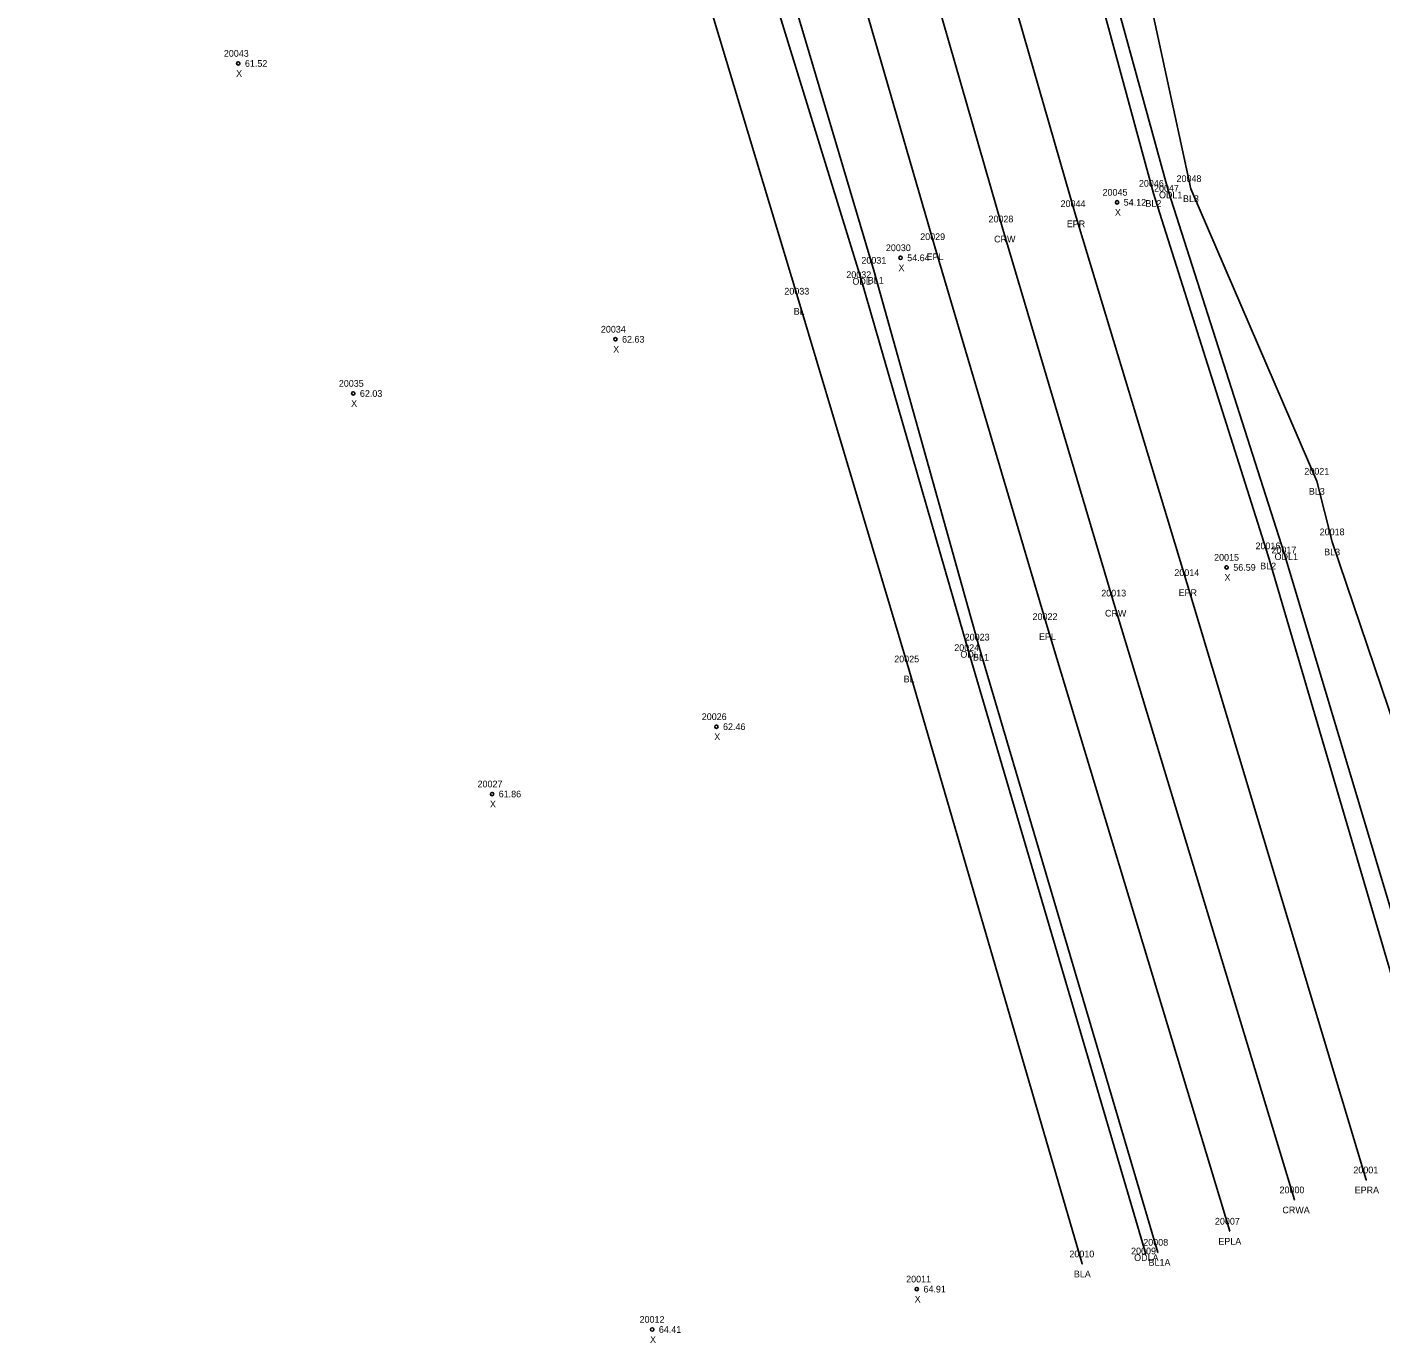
# Model space of a CAD drawing. Extents: x 2445178 to 2446260, y 791158 to 792318.
# Drawn here: x 2445670.7 to 2445873, y 791157.7 to 791354.3 of the extents above; entities that cross this region are included whole.
import ezdxf

# ---------------------------------------------------------------- set-up
doc = ezdxf.new("R2010")
doc.units = 0
for name, color, linetype in [('RD_DTM_BkLn1', 7, 'Continuous'), ('RD_EX_H2O', 7, 'Continuous'), ('RD_EX_H2O_txCode', 7, 'Continuous'), ('RD_EX_Road', 7, 'Continuous'), ('RD_EX_Road_txCode', 7, 'Continuous'), ('RD_Sketch8', 7, 'Continuous'), ('RD_SMD_Locator', 7, 'Continuous'), ('RD_SMD_Misc', 7, 'Continuous')]:
    doc.layers.add(name, color=color, linetype=linetype)

msp = doc.modelspace()

# ---------------------------------------------------------------- linework, layer by layer
at = {"layer": 'RD_DTM_BkLn1'}
for points in [[(2445860.1, 791179.04), (2445833.11, 791268.21), (2445816.53, 791324.11), (2445799.46, 791383.44), (2445783.89, 791440.59), (2445769.57, 791497.35), (2445755.95, 791556.11), (2445741.36, 791625.36), (2445732.84, 791671.31), (2445721.28, 791739.8), (2445717.39, 791765.43)], [(2445882.78, 791184.78), (2445856.18, 791275.27), (2445839.04, 791329.43), (2445822.96, 791388.68), (2445805.7, 791444.65), (2445792.52, 791499.62), (2445777.56, 791559.78), (2445760.75, 791635.11), (2445757, 791668.89), (2445761.65, 791682.26), (2445806.3, 791698.85), (2445844.78, 791714.67)], [(2445896.2, 791187.37), (2445865.75, 791277.36), (2445863.45, 791286.42), (2445844.64, 791330.14), (2445831.75, 791389.47), (2445816.24, 791445.72), (2445804.21, 791499.93), (2445790.09, 791561.7), (2445779.57, 791613.54), (2445773.51, 791630.61), (2445764.7, 791668.39), (2445768.27, 791675.25), (2445808.12, 791695.24), (2445844.78, 791714.67)], [(2445839.71, 791171.21), (2445812.99, 791261.63), (2445797.26, 791317.94), (2445780.39, 791374.8), (2445762.73, 791434.98), (2445748.42, 791490.93), (2445737.04, 791541.96), (2445736.07, 791553.56), (2445730.12, 791555.63), (2445697.6, 791546.96), (2445670.73, 791536.08)], [(2445828.38, 791169.47), (2445802.46, 791258.37), (2445786.04, 791313.32), (2445768.83, 791370.56), (2445749.12, 791431.66), (2445737.78, 791488.28), (2445729.51, 791541.48), (2445729.31, 791548.76), (2445698.8, 791542.8), (2445670.73, 791536.08)]]:
    msp.add_lwpolyline(points, dxfattribs=at)
at = {"layer": 'RD_EX_H2O'}
for points in [[(2445885.63, 791185.34), (2445858.54, 791275.66), (2445841.27, 791329.71), (2445824.98, 791389.05), (2445808.2, 791445.07), (2445795.15, 791500.08), (2445780.4, 791559.92), (2445764.43, 791632.51), (2445759.72, 791668.56), (2445764.88, 791679.11), (2445806.8, 791696.09), (2445844.78, 791714.67)], [(2445837.89, 791170.92), (2445811.42, 791261.06), (2445795.3, 791316.79), (2445777.82, 791373.49), (2445760.55, 791434.46), (2445746.47, 791490.55), (2445734.66, 791541.55), (2445732.29, 791551.98), (2445698.31, 791545.12), (2445670.73, 791536.08)]]:
    msp.add_lwpolyline(points, dxfattribs=at)
at = {"layer": 'RD_EX_Road'}
for points in [[(2445850.42, 791174.36), (2445823.13, 791264.7), (2445806.34, 791321.46), (2445789.41, 791379.89), (2445773.46, 791437.57), (2445759.36, 791494.22), (2445744.01, 791559.83), (2445740.09, 791577.64), (2445731.05, 791621.01), (2445722.21, 791669.43), (2445711, 791738.26), (2445706.49, 791765.2)], [(2445870.82, 791182.02), (2445844.02, 791271.27), (2445827.31, 791326.39), (2445810.32, 791385.52), (2445794.94, 791441.92), (2445780.98, 791497.5), (2445766.72, 791558.1), (2445751.9, 791628.3), (2445743.63, 791673.52), (2445732.07, 791741.61), (2445728.16, 791765.65)]]:
    msp.add_lwpolyline(points, dxfattribs=at)
at = {"layer": 'RD_SMD_Locator'}
for centre, radius in [((2445702.28, 791348.85), 0.25), ((2445841.27, 791329.71), 0.001), ((2445844.64, 791330.14), 0.001), ((2445833.59, 791328.1), 0.25), ((2445839.04, 791329.43), 0.001), ((2445827.31, 791326.39), 0.001), ((2445816.53, 791324.11), 0.001), ((2445806.34, 791321.46), 0.001), ((2445801.24, 791319.81), 0.25), ((2445797.26, 791317.94), 0.001), ((2445795.3, 791316.79), 0.001), ((2445786.04, 791313.32), 0.001), ((2445758.63, 791307.64), 0.25), ((2445719.46, 791299.54), 0.25), ((2445863.45, 791286.42), 0.001), ((2445865.75, 791277.36), 0.001), ((2445856.18, 791275.27), 0.001), ((2445858.54, 791275.66), 0.001), ((2445849.96, 791273.55), 0.25), ((2445844.02, 791271.27), 0.001), ((2445833.11, 791268.21), 0.001), ((2445823.13, 791264.7), 0.001), ((2445811.42, 791261.06), 0.001), ((2445812.99, 791261.63), 0.001), ((2445802.46, 791258.37), 0.001), ((2445773.72, 791249.75), 0.25), ((2445740.2, 791239.69), 0.25), ((2445870.82, 791182.02), 0.001), ((2445860.1, 791179.04), 0.001), ((2445850.42, 791174.36), 0.001), ((2445837.89, 791170.92), 0.001), ((2445839.71, 791171.21), 0.001), ((2445828.38, 791169.47), 0.001), ((2445803.67, 791165.71), 0.25), ((2445764.13, 791159.68), 0.25)]:
    msp.add_circle(centre, radius, dxfattribs=at)

# ---------------------------------------------------------------- texts
at = {"layer": 'RD_EX_H2O_txCode'}
for s, p in [('20047', (2445839.12, 791329.71)), ('ODL1', (2445839.86, 791328.71)), ('20032', (2445793.14, 791316.79)), ('ODL', (2445794.05, 791315.79)), ('20017', (2445856.66, 791275.66)), ('ODL1', (2445857.13, 791274.66)), ('20024', (2445809.27, 791261.06)), ('ODL', (2445810.18, 791260.06)), ('20009', (2445835.69, 791170.92)), ('ODLA', (2445836.15, 791169.92))]:
    msp.add_text(s, height=1, dxfattribs=at).set_placement(p)
at = {"layer": 'RD_EX_Road_txCode'}
for s, p in [('20044', (2445825.15, 791327.39)), ('20029', (2445804.18, 791322.46)), ('EPR', (2445826.08, 791324.39)), ('EPL', (2445805.13, 791319.46)), ('20014', (2445842.15, 791272.27)), ('EPR', (2445842.79, 791269.27)), ('20022', (2445820.97, 791265.7)), ('EPL', (2445821.92, 791262.7)), ('20001', (2445868.9, 791183.02)), ('EPRA', (2445869.1, 791180.02)), ('20007', (2445848.22, 791175.36)), ('EPLA', (2445848.73, 791172.36))]:
    msp.add_text(s, height=1, dxfattribs=at).set_placement(p)
at = {"layer": 'RD_Sketch8'}
for s, p in [('20043', (2445700.13, 791349.85)), ('X', (2445701.97, 791346.85)), ('61.52', (2445703.28, 791348.35)), ('20045', (2445831.43, 791329.1)), ('54.12', (2445834.59, 791327.6)), ('X', (2445833.27, 791326.1)), ('20030', (2445799.05, 791320.81)), ('54.64', (2445802.24, 791319.31)), ('X', (2445800.93, 791317.81)), ('20034', (2445756.47, 791308.64)), ('62.63', (2445759.63, 791307.14)), ('X', (2445758.31, 791305.64)), ('20035', (2445717.31, 791300.54)), ('62.03', (2445720.46, 791299.04)), ('X', (2445719.15, 791297.54)), ('20015', (2445848.09, 791274.55)), ('56.59', (2445850.96, 791273.05)), ('X', (2445849.65, 791271.55)), ('20026', (2445771.54, 791250.75)), ('X', (2445773.41, 791247.75)), ('62.46', (2445774.72, 791249.25)), ('20027', (2445738.04, 791240.69)), ('X', (2445739.89, 791237.69)), ('61.86', (2445741.2, 791239.19)), ('20011', (2445802.08, 791166.71)), ('64.91', (2445804.67, 791165.21)), ('X', (2445803.35, 791163.71)), ('20012', (2445762.25, 791160.68)), ('64.41', (2445765.13, 791159.18)), ('X', (2445763.81, 791157.68))]:
    msp.add_text(s, height=1, dxfattribs=at).set_placement(p)
at = {"layer": 'RD_SMD_Misc'}
for s, p in [('20048', (2445842.48, 791331.14)), ('20046', (2445836.86, 791330.43)), ('BL2', (2445837.83, 791327.43)), ('BL3', (2445843.44, 791328.14)), ('20028', (2445814.38, 791325.11)), ('CRW', (2445815.22, 791322.11)), ('20031', (2445795.39, 791318.94)), ('BL1', (2445796.34, 791315.94)), ('20033', (2445783.88, 791314.32)), ('BL', (2445785.28, 791311.32)), ('20021', (2445861.58, 791287.42)), ('BL3', (2445862.25, 791284.42)), ('20018', (2445863.87, 791278.36)), ('20016', (2445854.28, 791276.27)), ('BL3', (2445864.54, 791275.36)), ('BL2', (2445854.98, 791273.27)), ('20013', (2445831.23, 791269.21)), ('CRW', (2445831.79, 791266.21)), ('20023', (2445810.83, 791262.63)), ('20025', (2445800.3, 791259.37)), ('BL1', (2445812.07, 791259.63)), ('BL', (2445801.7, 791256.37)), ('20000', (2445857.87, 791180.04)), ('CRWA', (2445858.3, 791177.04)), ('20008', (2445837.51, 791172.21)), ('20010', (2445826.47, 791170.47)), ('BL1A', (2445838.3, 791169.21)), ('BLA', (2445827.14, 791167.47))]:
    msp.add_text(s, height=1, dxfattribs=at).set_placement(p)

doc.saveas('drawing.dxf')
